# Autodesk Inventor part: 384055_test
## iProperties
Created: 2006-01
Part Number: 384055_test
Material: Standard
Document SubType Name: Modeling
Designer: I.Baliuc
Manufacturer: Standard
Standards Organization: Custom
Description: Elektra - Gießharz
Density: 7.84 g/cm^3
Mass: 616.044 g
Surface Area: 1275.33 cm^2
Volume: 78.577 cm^3
dX*dY*dZ: 52mm x 66mm x 78mm
Flaeche: 127533 mm²
Volumen: 78577 mm³
Author: AHausen
Revision Number: 384055 - 384085
Comments: 384085: Härter PU88 - 37,5 gr 384055: Gießharz PU123 Beige - 131,2 gr
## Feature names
1. Basis1
2. Extrusion1
3. Extrusion2
